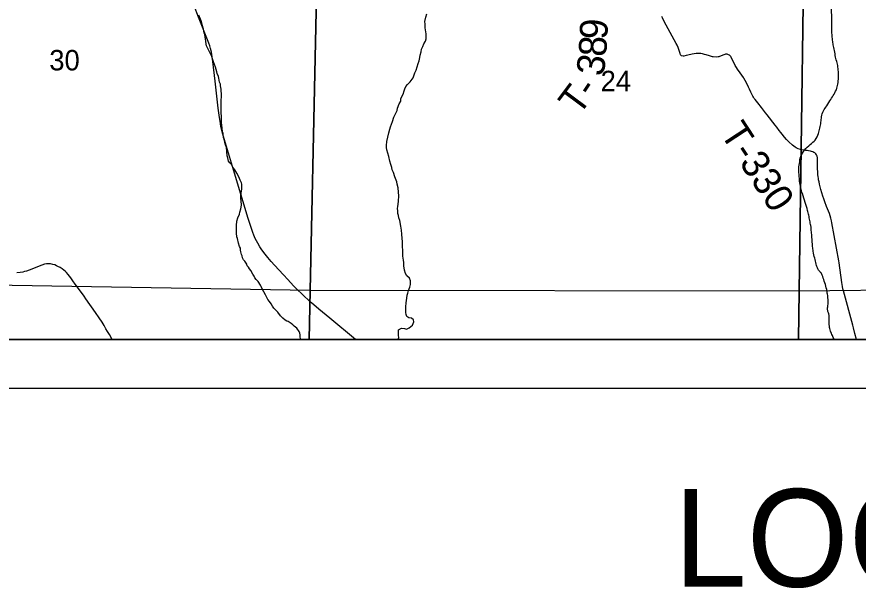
# Model space of a CAD drawing. Extents: x 0 to 34, y 0 to 22.
# Drawn here: x 19.582 to 21.303, y 13.091 to 14.261 of the extents above; entities that cross this region are included whole.
import ezdxf

# ---------------------------------------------------------------- set-up
doc = ezdxf.new("R2010")
doc.units = 0
for name, color, linetype in [('GM_X_Corporation', 7, 'Continuous'), ('GM_X_County_Road', 7, 'Continuous'), ('GM_X_Minor_River', 7, 'Continuous'), ('GM_X_Section_Text', 7, 'Continuous'), ('GM_X_Township_Road', 7, 'Continuous'), ('GM_X_Township_Road_Text', 7, 'Continuous'), ('SH_Data', 7, 'Continuous'), ('SH_Text', 7, 'Continuous')]:
    doc.layers.add(name, color=color, linetype=linetype)

msp = doc.modelspace()

# ---------------------------------------------------------------- linework, layer by layer
at = {"layer": 'GM_X_Corporation'}
for points in [[(18.6, 14.6606), (18.6, 13.6), (24.2109, 13.6), (24.2228, 14.2453), (24.2265, 14.4444), (24.2301, 14.5912), (22.9003, 14.6033), (22.3464, 14.612), (21.314, 14.623), (21.1282, 14.6279), (20.2571, 14.6508), (20.2016, 14.6512), (19.8855, 14.6528), (19.4007, 14.6554), (18.9216, 14.6592)], [(19.1768, 14.6588), (20.2028, 14.6536), (20.1822, 13.7001), (19.1654, 13.7176)], [(20.2028, 14.6536), (21.1958, 14.6279), (21.1828, 13.6991), (20.1822, 13.7001)], [(21.1958, 14.6279), (22.2045, 14.6168), (22.1889, 13.7096), (21.1828, 13.6991)], [(19.1641, 13.6), (20.1804, 13.6), (20.1822, 13.7001), (19.1654, 13.7176)], [(21.1814, 13.6), (22.1867, 13.6), (22.1889, 13.7096), (21.1828, 13.6991)], [(20.1804, 13.6), (21.1814, 13.6), (21.1828, 13.6991), (20.1822, 13.7001)]]:
    msp.add_lwpolyline(points, close=True, dxfattribs=at)
at = {"layer": 'GM_X_County_Road'}
msp.add_lwpolyline([(20.2754, 13.6), (20.2229, 13.6436), (20.2003, 13.6624), (20.185, 13.6753), (20.1773, 13.6822), (20.1714, 13.6876), (20.1652, 13.6935), (20.1566, 13.7017), (20.1484, 13.71), (20.1364, 13.7227), (20.1276, 13.7324), (20.1097, 13.7521), (20.1028, 13.7597), (20.0958, 13.7681), (20.0902, 13.7748), (20.0835, 13.7838), (20.0795, 13.7896), (20.0751, 13.797), (20.0725, 13.8018), (20.0699, 13.8069), (20.0672, 13.8133), (20.0649, 13.8192), (20.0595, 13.8355), (20.0557, 13.8478), (20.0254, 13.9477), (20.0048, 14.0155), (20.0028, 14.0226), (20.0007, 14.0309), (19.9995, 14.037), (19.998, 14.047), (19.9969, 14.0546), (19.9945, 14.0735), (19.9915, 14.0982), (19.9879, 14.1292), (19.9833, 14.1693), (19.9819, 14.1789), (19.9803, 14.1882), (19.9785, 14.1956), (19.9769, 14.2011), (19.975, 14.2067), (19.9539, 14.2601), (19.9449, 14.2833)], dxfattribs=at)
at = {"layer": 'GM_X_Minor_River'}
for points in [[(20.0004, 14.0795), (20.0006, 14.0871), (20.0011, 14.0997), (20, 14.1122), (19.9987, 14.1191), (19.9986, 14.1229), (19.997, 14.127), (19.9957, 14.1353), (19.9948, 14.1384), (19.9924, 14.1448), (19.9912, 14.1478), (19.9887, 14.1576), (19.9847, 14.1682), (19.9826, 14.1746), (19.981, 14.1792), (19.9774, 14.1878), (19.9726, 14.1969), (19.9703, 14.201), (19.9694, 14.2048), (19.9689, 14.2105), (19.968, 14.215), (19.9667, 14.2241), (19.9655, 14.2275), (19.9641, 14.2351), (19.9621, 14.2419), (19.9592, 14.2521), (19.9548, 14.2638)], [(20.3679, 14.0935), (20.3727, 14.102), (20.3749, 14.1089), (20.376, 14.1135), (20.3782, 14.1177), (20.3815, 14.1219), (20.3871, 14.1277), (20.3931, 14.1358), (20.3963, 14.1457), (20.3989, 14.1515), (20.4011, 14.158), (20.4033, 14.1653), (20.4055, 14.1706), (20.4065, 14.1771), (20.4076, 14.1821), (20.4094, 14.189), (20.41, 14.1943), (20.413, 14.1997), (20.4152, 14.205), (20.4181, 14.2108), (20.4196, 14.2158), (20.4199, 14.2207), (20.4194, 14.2261), (20.4177, 14.2382), (20.4173, 14.2454), (20.4172, 14.2512), (20.4189, 14.2599), (20.4207, 14.2668)], [(20.163, 13.6), (20.1629, 13.6011), (20.1621, 13.6056), (20.162, 13.6094), (20.1615, 13.6128), (20.1599, 13.6162), (20.1548, 13.6229), (20.1498, 13.627), (20.1467, 13.63), (20.1436, 13.6326), (20.1374, 13.637), (20.1344, 13.6377), (20.1309, 13.6399), (20.1267, 13.6436), (20.1216, 13.6484), (20.1162, 13.6563), (20.1115, 13.6608), (20.108, 13.6645), (20.1056, 13.6686), (20.1029, 13.6727), (20.099, 13.6776), (20.0955, 13.6817), (20.0935, 13.6858), (20.0907, 13.6915), (20.0875, 13.6979), (20.0843, 13.7035), (20.0823, 13.7084), (20.0811, 13.7114), (20.076, 13.7185), (20.0718, 13.723), (20.069, 13.7264), (20.0678, 13.7298), (20.0651, 13.7335), (20.0607, 13.7414), (20.0584, 13.7444), (20.056, 13.7478), (20.0537, 13.7508), (20.0525, 13.7542), (20.0485, 13.7602), (20.0458, 13.7631), (20.0438, 13.7669), (20.043, 13.7711), (20.0418, 13.7741), (20.0405, 13.7794), (20.04, 13.7828), (20.0396, 13.787), (20.038, 13.7907), (20.0355, 13.7971), (20.0334, 13.8066), (20.0326, 13.81), (20.032, 13.818), (20.0316, 13.821), (20.0317, 13.8302), (20.032, 13.8336), (20.0322, 13.842), (20.0343, 13.8493), (20.0375, 13.8569), (20.0386, 13.8608), (20.0403, 13.8677), (20.0416, 13.8753), (20.0414, 13.8837), (20.0402, 13.8886), (20.0404, 13.8951), (20.0423, 13.9088), (20.0426, 13.9123), (20.0429, 13.918), (20.0421, 13.921), (20.0393, 13.9259), (20.0377, 13.9293), (20.0353, 13.9361), (20.0321, 13.9406), (20.0285, 13.9473), (20.0243, 13.9526), (20.0211, 13.9586), (20.018, 13.9619), (20.0156, 13.9653), (20.0144, 13.9687), (20.0136, 13.9717), (20.0127, 13.9759), (20.0121, 13.9846), (20.0112, 13.9934), (20.0087, 14.0005), (20.0062, 14.01), (20.0054, 14.013), (20.0044, 14.0217), (20.0032, 14.0251), (20.0023, 14.0335), (20.0013, 14.0437), (20.0008, 14.0468), (20.001, 14.0529), (20.001, 14.0559), (20.0004, 14.065), (20.0005, 14.0761), (20.0004, 14.0795)], [(20.3625, 13.6), (20.3636, 13.6038), (20.3632, 13.608), (20.363, 13.6198), (20.369, 13.623), (20.3755, 13.6227), (20.3797, 13.6212), (20.3849, 13.6236), (20.3917, 13.6294), (20.3942, 13.6359), (20.3938, 13.6401), (20.3896, 13.6434), (20.3843, 13.6441), (20.38, 13.6471), (20.3785, 13.6513), (20.378, 13.6555), (20.3779, 13.6669), (20.3789, 13.6753), (20.3799, 13.6848), (20.3806, 13.6905), (20.382, 13.6947), (20.3838, 13.7001), (20.386, 13.707), (20.3878, 13.7127), (20.3877, 13.7203), (20.3853, 13.7256), (20.38, 13.7301), (20.3776, 13.735), (20.3753, 13.7422), (20.374, 13.7506), (20.3739, 13.7574), (20.3731, 13.7627), (20.3722, 13.7703), (20.3718, 13.7749), (20.3717, 13.7795), (20.372, 13.784), (20.3716, 13.7886), (20.3711, 13.7962), (20.371, 13.8004), (20.3705, 13.8069), (20.37, 13.8156), (20.3692, 13.8236), (20.3679, 13.8323), (20.3659, 13.8434), (20.3639, 13.849), (20.3631, 13.8536), (20.3619, 13.8578), (20.3614, 13.8631), (20.3613, 13.868), (20.3617, 13.8722), (20.3623, 13.8768), (20.3634, 13.8833), (20.3636, 13.894), (20.3631, 13.9016), (20.3622, 13.9107), (20.3606, 13.9183), (20.3594, 13.9228), (20.3559, 13.9327), (20.3527, 13.9422), (20.3504, 13.9475), (20.3491, 13.9524), (20.3472, 13.9584), (20.3456, 13.9649), (20.3435, 13.9748), (20.3412, 13.9812), (20.3395, 13.9884), (20.3383, 13.993), (20.3383, 13.9975), (20.3393, 14.0052), (20.3414, 14.014), (20.3432, 14.0231), (20.3454, 14.0304), (20.3468, 14.0357), (20.3505, 14.0461), (20.3534, 14.0549), (20.3603, 14.0691), (20.3607, 14.0736), (20.3647, 14.0825), (20.3676, 14.0882), (20.3679, 14.0935)]]:
    msp.add_lwpolyline(points, dxfattribs=at)
msp.add_spline([(21.2544, 13.6), (21.2506, 13.6084), (21.247, 13.617), (21.2445, 13.6276), (21.2442, 13.6398), (21.2439, 13.6497), (21.2434, 13.6528), (21.2423, 13.656), (21.2412, 13.6591), (21.2407, 13.6622), (21.2419, 13.6721), (21.2417, 13.685), (21.2403, 13.6952), (21.2374, 13.709), (21.233, 13.7227), (21.2282, 13.7349), (21.2266, 13.7374), (21.2246, 13.7396), (21.2226, 13.7419), (21.2211, 13.7444), (21.2178, 13.7544), (21.2145, 13.7665), (21.2116, 13.7806), (21.2102, 13.7901), (21.2089, 13.8095), (21.2079, 13.8202), (21.2065, 13.8331), (21.2044, 13.8437), (21.2026, 13.8544), (21.2001, 13.8643), (21.1953, 13.8807), (21.1894, 13.8986), (21.1862, 13.9108), (21.1837, 13.9241), (21.1827, 13.9362), (21.182, 13.9461), (21.1833, 13.9605), (21.1861, 13.9746), (21.1939, 13.9878), (21.2054, 13.9994), (21.2154, 14.0084), (21.2224, 14.0216), (21.2252, 14.033), (21.2272, 14.0447), (21.2285, 14.0561), (21.2324, 14.0682), (21.2394, 14.0784), (21.2475, 14.0916), (21.2541, 14.1021), (21.26, 14.1146), (21.2624, 14.1259), (21.2633, 14.1407), (21.2627, 14.1514), (21.2609, 14.1639), (21.258, 14.175), (21.2555, 14.1883), (21.253, 14.2008), (21.2516, 14.2104), (21.2502, 14.2214), (21.2496, 14.2332), (21.2497, 14.2457), (21.2498, 14.2582), (21.2489, 14.2727), (21.2487, 14.2879), (21.2481, 14.3004), (21.2455, 14.3099), (21.2407, 14.324), (21.2371, 14.3366), (21.2338, 14.3484), (21.2305, 14.3598), (21.225, 14.3736), (21.2198, 14.3892), (21.2178, 14.4052), (21.2179, 14.4189), (21.2177, 14.4322)], degree=3, dxfattribs=at)
at = {"layer": 'GM_X_Township_Road'}
for points in [[(21.3, 13.6), (21.2969, 13.612), (21.294, 13.6237), (21.2924, 13.6293), (21.2734, 13.6997), (21.2724, 13.7038), (21.2715, 13.7082), (21.2707, 13.7123), (21.2699, 13.7169), (21.2645, 13.7569), (21.2638, 13.7613), (21.2498, 13.8386), (21.2489, 13.8428), (21.2477, 13.8481), (21.2464, 13.853), (21.2449, 13.8577), (21.2389, 13.8725), (21.2351, 13.8821), (21.233, 13.8878), (21.231, 13.8937), (21.2289, 13.9003), (21.2273, 13.9068), (21.2258, 13.9129), (21.2246, 13.9177), (21.2234, 13.9228), (21.2226, 13.9266), (21.222, 13.9296), (21.2215, 13.9334), (21.2212, 13.9369), (21.2208, 13.9424), (21.2204, 13.95), (21.2202, 13.9602), (21.2203, 13.9672), (21.2201, 13.9717), (21.2193, 13.9752), (21.2187, 13.9767), (21.2179, 13.9784), (21.2169, 13.9798), (21.2159, 13.9808), (21.2145, 13.9819), (21.2127, 13.9829), (21.2105, 13.9839), (21.2077, 13.9849), (21.2061, 13.9855), (21.2017, 13.9865), (21.1992, 13.9869), (21.1959, 13.9872), (21.1924, 13.9877), (21.1875, 13.9884), (21.1857, 13.9888), (21.181, 13.9902), (21.1792, 13.991), (21.1769, 13.9921), (21.1743, 13.9937), (21.1716, 13.9956), (21.1689, 13.9978), (21.1616, 14.0046), (21.157, 14.0093), (21.1526, 14.0144), (21.148, 14.0203), (21.1452, 14.0237), (21.1419, 14.0282), (21.137, 14.0347), (21.1338, 14.039), (21.1173, 14.0603), (21.1142, 14.0643), (21.1057, 14.0748), (21.0982, 14.0842), (21.0925, 14.0913), (21.0908, 14.0936), (21.0892, 14.0962), (21.0879, 14.0983), (21.0866, 14.1007), (21.0838, 14.1066), (21.0811, 14.1122), (21.0791, 14.1165), (21.0762, 14.1227), (21.0725, 14.13), (21.0697, 14.1347), (21.0688, 14.1363), (21.0655, 14.1412), (21.0618, 14.1462), (21.0565, 14.1535), (21.0542, 14.1571), (21.0521, 14.1608), (21.0434, 14.1782), (21.0428, 14.1791), (21.0415, 14.1806), (21.0399, 14.182), (21.0385, 14.1829), (21.0368, 14.1836), (21.0353, 14.184), (21.0337, 14.184), (21.0323, 14.1839), (21.0306, 14.1835), (21.0283, 14.1827), (21.0234, 14.1808), (21.0185, 14.1789), (21.0168, 14.1784), (21.0127, 14.1778), (21.007, 14.1785), (21.0056, 14.1788), (20.9995, 14.1806), (20.9928, 14.1827), (20.9889, 14.1838), (20.9853, 14.1847), (20.9817, 14.1854), (20.9783, 14.1857), (20.9718, 14.1854), (20.9637, 14.1842), (20.9609, 14.1836), (20.9518, 14.1814), (20.9467, 14.1804), (20.9453, 14.1802), (20.9422, 14.1806), (20.941, 14.1812), (20.9405, 14.1817), (20.9399, 14.183), (20.9392, 14.1856), (20.9369, 14.1936), (20.9354, 14.1977), (20.9331, 14.2028), (20.9313, 14.2063), (20.9105, 14.2434), (20.9078, 14.2486), (20.9029, 14.2586), (20.9018, 14.261)], [(19.7003, 13.7156), (19.6985, 13.7181), (19.6927, 13.726), (19.6871, 13.733), (19.6839, 13.737), (19.6809, 13.7401), (19.6785, 13.7421), (19.6751, 13.7445), (19.671, 13.7471), (19.6665, 13.7495), (19.6636, 13.751), (19.6597, 13.7526), (19.6561, 13.7537), (19.6515, 13.7547), (19.6471, 13.755), (19.6431, 13.7549), (19.6391, 13.754), (19.6335, 13.7522), (19.6279, 13.7499), (19.6129, 13.7439), (19.6076, 13.7419), (19.6023, 13.7401), (19.5982, 13.739), (19.5943, 13.738), (19.5893, 13.737), (19.5821, 13.7363)], [(19.7773, 13.6), (19.7763, 13.6017), (19.7716, 13.61), (19.7679, 13.6163), (19.7646, 13.6219), (19.7607, 13.6284), (19.7567, 13.6353), (19.7504, 13.6447), (19.743, 13.6552), (19.7232, 13.6836), (19.7197, 13.6888), (19.7003, 13.7156)]]:
    msp.add_lwpolyline(points, dxfattribs=at)
at = {"layer": 'SH_Data'}
for points in [[(18.5, 20.5), (25.5, 20.5), (25.5, 13.5), (18.5, 13.5)], [(18.6, 20.4), (25.4, 20.4), (25.4, 13.6), (18.6, 13.6)]]:
    msp.add_lwpolyline(points, close=True, dxfattribs=at)

# ---------------------------------------------------------------- texts
at = {"layer": 'GM_X_Section_Text'}
for s, p in [('30', (19.6487, 14.1509)), ('24', (20.7766, 14.1083))]:
    msp.add_text(s, height=0.04186, rotation=0, dxfattribs=at).set_placement(p)
at = {"layer": 'GM_X_Township_Road_Text'}
for s, height, rotation, p in [('9', 0.0568, 87.1598, (20.7899, 14.2133)), ('8', 0.0568, 86.8258, (20.7879, 14.178)), ('3', 0.0568, 81.2031, (20.7819, 14.1374)), ('T', 0.0568, 53.2621, (20.732, 14.0563)), ('-', 0.0568, 56.2593, (20.7593, 14.093)), ('T-330', 0.05682, 303.2238, (21.0197, 14.0222))]:
    msp.add_text(s, height=height, rotation=rotation, dxfattribs=at).set_placement(p)
at = {"layer": 'SH_Text'}
msp.add_text('LOCATION MAP', height=0.2, dxfattribs=at).set_placement((20.9269, 13.0938))

doc.saveas('drawing.dxf')
